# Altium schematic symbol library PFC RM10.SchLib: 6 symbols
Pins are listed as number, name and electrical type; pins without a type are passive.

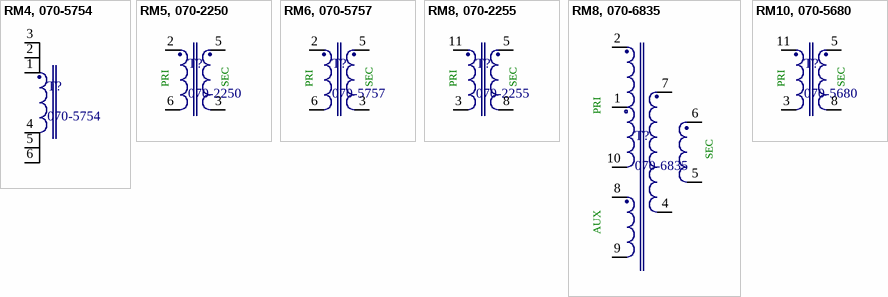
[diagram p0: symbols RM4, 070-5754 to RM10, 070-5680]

## RM4, 070-5754
designator T?, comment 070-5754
Transformer 6-Terminal , THT, Vertical, RM Style Bobbins, RM4; Manufacturer: Würth Elektronik Midcom; Core: 150-2620
footprint RM4_5754 (THT, Body 11.44x11.44mm, 6Pin, Pitch 2.54mm)
pins: 1, 2, 3, 4, 5, 6

## RM5, 070-2250
designator T?, comment 070-2250
Transformer 6-Terminal , THT, Vertical, RM Style Bobbins, RM5; Manufacturer: Würth Elektronik Midcom; Core: 150-2378
footprint RM5_2250 (THT, Body 13.97x13.97mm, 6Pin, Pitch 2.54mm)
pins: 2, 3, 5, 6

## RM6, 070-5757
designator T?, comment 070-5757
Transformer 6-Terminal , THT, Vertical, RM Style Bobbins, RM6; Manufacturer: Würth Elektronik Midcom; Core: 150-2622
footprint RM6_5757 (THT, Body 16.64x17.65mm, 6Pin, Pitch 2.54mm)
pins: 2, 3, 5, 6

## RM8, 070-2255
designator T?, comment 070-2255
Transformer 12-Terminal , THT, Vertical, RM Style Bobbins, RM8; Manufacturer: Würth Elektronik Midcom; Core: 150-2623
footprint RM8_2255 (THT, Body 21.59x12.59mm, 12Pin, Pitch 2.54mm)
pins: 3, 5, 8, 11

## RM8, 070-6835
designator T?, comment 070-6835
Transformer 10-Terminal , THT, Vertical, RM Style Bobbins, RM8; Manufacturer: Würth Elektronik Midcom; Core: 150-2623
footprint RM8_6835 (THT, Body 24.64X24.64mm, 10Pin, Pitch 2.54mm)
pins: 1, 2, 4, 5, 6, 7, 8, 9, 10

## RM10, 070-5680
designator T?, comment 070-5680
Transformer 12-Terminal , THT, Vertical, RM Style Bobbins, RM10; Manufacturer: Würth Elektronik Midcom; Core: 150-2624
footprint RM10_5680 (THT, Body 26.16x26.16mm, 12Pin, Pitch 2.54mm)
pins: 3, 5, 8, 11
